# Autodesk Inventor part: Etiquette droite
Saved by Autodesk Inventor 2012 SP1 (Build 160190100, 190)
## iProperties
Created: 2014-12
Part Number: Etiquette droite
Material: Default
Document SubType Name: Modeling
Designer: Bruno
Density: 1 g/cm^3
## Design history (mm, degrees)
node "Etiquette droite1"
node "Etiquette droite"
node "Base1"
